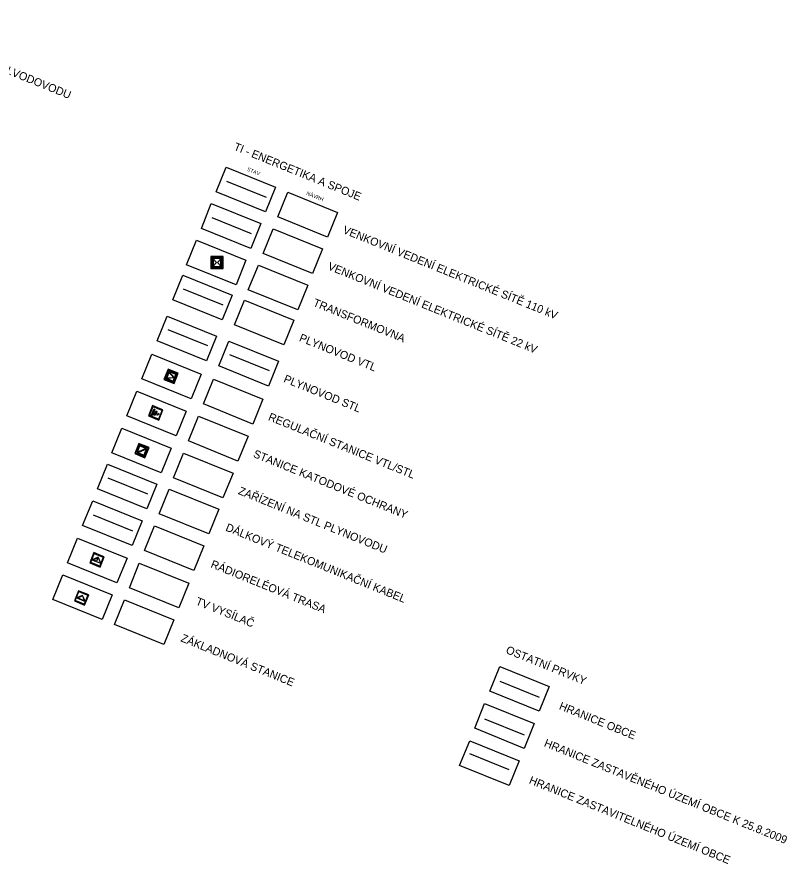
# Model space of a CAD drawing. Extents: x -522763 to -519637, y -1191176 to -1188936.
# Drawn here: x -521081 to -519637, y -1191176 to -1189587 of the extents above; entities that cross this region are included whole.
import ezdxf

# ---------------------------------------------------------------- set-up
doc = ezdxf.new("R2010")
doc.units = 0
for name, color, linetype in [('elved_110_s', 7, 'Continuous'), ('elved_22_s', 7, 'Continuous'), ('hr_ku_P_s', 7, 'Continuous'), ('hr_zast_uz_P_n', 7, 'Continuous'), ('HZU_P_s', 7, 'Continuous'), ('Implicitní', 7, 'Continuous'), ('kabel_dal_s', 7, 'Continuous'), ('ložisk_nerost', 7, 'Continuous'), ('plyn_STL_n', 7, 'Continuous'), ('plyn_STL_s', 7, 'Continuous'), ('plyn_VTL_s', 7, 'Continuous'), ('plyn_zar_STL_s', 7, 'Continuous'), ('RR_trasa_s', 7, 'Continuous'), ('stan_KO_s', 7, 'Continuous'), ('TV_vysilac_s', 7, 'Continuous'), ('zakl_stan_s', 7, 'Continuous')]:
    doc.layers.add(name, color=color, linetype=linetype)

msp = doc.modelspace()

# ---------------------------------------------------------------- linework, layer by layer
at = {"layer": 'elved_110_s'}
msp.add_line((-520688.1, -1189895), (-520613.9, -1189925.1), dxfattribs=at)
at = {"layer": 'elved_22_s'}
msp.add_line((-520715.9, -1189963.3), (-520641.8, -1189993.3), dxfattribs=at)
at = {"layer": 'hr_ku_P_s'}
msp.add_line((-520175.8, -1190832.8), (-520101.7, -1190862.8), dxfattribs=at)
at = {"layer": 'hr_zast_uz_P_n'}
msp.add_line((-520232.8, -1190968.4), (-520158.6, -1190998.4), dxfattribs=at)
at = {"layer": 'HZU_P_s'}
msp.add_line((-520204.4, -1190903.3), (-520130.3, -1190933.4), dxfattribs=at)
at = {"layer": 'Implicitní'}
for points in [[(-520688.9, -1189869.1), (-520596.2, -1189906.7), (-520615, -1189953), (-520707.7, -1189915.5)], [(-520573, -1189916.1), (-520480.4, -1189953.7), (-520499.1, -1190000), (-520591.8, -1189962.4)], [(-520716.8, -1189937.4), (-520624.1, -1189974.9), (-520642.9, -1190021.3), (-520735.5, -1189983.7)], [(-520600.9, -1189984.3), (-520508.2, -1190021.9), (-520527, -1190068.2), (-520619.7, -1190030.7)], [(-520744.4, -1190005.7), (-520651.8, -1190043.2), (-520670.5, -1190089.6), (-520763.2, -1190052)], [(-520628.6, -1190052.6), (-520535.9, -1190090.2), (-520554.7, -1190136.5), (-520647.4, -1190099)], [(-520770.4, -1190071.4), (-520677.7, -1190109), (-520696.5, -1190155.3), (-520789.2, -1190117.7)], [(-520654.6, -1190118.3), (-520561.9, -1190155.9), (-520580.7, -1190202.2), (-520673.4, -1190164.7)], [(-520799.6, -1190148.4), (-520706.9, -1190186), (-520725.7, -1190232.3), (-520818.4, -1190194.8)], [(-520683.7, -1190195.4), (-520591.1, -1190233), (-520609.8, -1190279.3), (-520702.5, -1190241.7)], [(-520828.5, -1190219.7), (-520735.8, -1190257.3), (-520754.6, -1190303.6), (-520847.3, -1190266.1)], [(-520712.6, -1190266.7), (-520620, -1190304.2), (-520638.7, -1190350.6), (-520731.4, -1190313)], [(-520856.6, -1190289), (-520763.9, -1190326.6), (-520782.7, -1190372.9), (-520875.4, -1190335.4)], [(-520740.7, -1190336), (-520648, -1190373.5), (-520666.8, -1190419.9), (-520759.5, -1190382.3)], [(-520884.7, -1190358.3), (-520792, -1190395.9), (-520810.8, -1190442.2), (-520903.4, -1190404.7)], [(-520768.8, -1190405.3), (-520676.1, -1190442.8), (-520694.9, -1190489.2), (-520787.6, -1190451.6)], [(-520911.4, -1190425.7), (-520818.8, -1190463.3), (-520837.5, -1190509.6), (-520930.2, -1190472)], [(-520795.6, -1190472.7), (-520702.9, -1190510.2), (-520721.7, -1190556.6), (-520814.4, -1190519)], [(-520939.3, -1190494.6), (-520846.7, -1190532.1), (-520865.4, -1190578.5), (-520958.1, -1190540.9)], [(-520939.3, -1190494.6), (-520846.7, -1190532.1), (-520865.4, -1190578.5), (-520958.1, -1190540.9)], [(-520823.5, -1190541.5), (-520730.8, -1190579.1), (-520749.6, -1190625.4), (-520842.3, -1190587.9)], [(-520967.6, -1190564.3), (-520874.9, -1190601.9), (-520893.7, -1190648.2), (-520986.4, -1190610.7)], [(-520851.8, -1190611.3), (-520759.1, -1190648.8), (-520777.9, -1190695.2), (-520870.5, -1190657.6)], [(-520995.5, -1190633.2), (-520902.8, -1190670.7), (-520921.6, -1190717.1), (-521014.3, -1190679.5)], [(-520995.5, -1190633.2), (-520902.8, -1190670.7), (-520921.6, -1190717.1), (-521014.3, -1190679.5)], [(-520879.7, -1190680.1), (-520787, -1190717.7), (-520805.8, -1190764), (-520898.4, -1190726.5)], [(-520176, -1190805.2), (-520083.3, -1190842.7), (-520102.1, -1190889.1), (-520194.8, -1190851.5)], [(-520204.2, -1190874.7), (-520111.5, -1190912.2), (-520130.3, -1190958.6), (-520222.9, -1190921)], [(-520232.3, -1190944.2), (-520139.6, -1190981.8), (-520158.4, -1191028.1), (-520251.1, -1190990.5)]]:
    msp.add_lwpolyline(points, close=True, dxfattribs=at)
at = {"layer": 'kabel_dal_s'}
msp.add_line((-520910.6, -1190451.6), (-520836.5, -1190481.7), dxfattribs=at)
at = {"layer": 'ložisk_nerost'}
for p, q in [((-520714.1, -1190047.7), (-520713.4, -1190047.7)), ((-520713.4, -1190047.7), (-520714.1, -1190047.7)), ((-520706.8, -1190047.7), (-520713.4, -1190041.1)), ((-520713.4, -1190054.4), (-520706.8, -1190047.7)), ((-520698.8, -1190041.1), (-520705.4, -1190047.7)), ((-520705.4, -1190047.7), (-520698.8, -1190054.4)), ((-520698.1, -1190047.7), (-520698.8, -1190047.7)), ((-520698.8, -1190047.7), (-520698.1, -1190047.7))]:
    msp.add_line(p, q, dxfattribs=at)
for points in [[(-520706.2, -1190036.3), (-520717.6, -1190036.3), (-520717.6, -1190059.2), (-520694.7, -1190059.2), (-520694.7, -1190036.3), (-520706.1, -1190036.3)], [(-520716.2, -1190037.7), (-520696.1, -1190037.7), (-520696.1, -1190057.8), (-520716.2, -1190057.8), (-520716.2, -1190037.7)], [(-520706.1, -1190037.7), (-520696.1, -1190037.7), (-520696.1, -1190057.8), (-520716.2, -1190057.8), (-520716.2, -1190037.7), (-520706.2, -1190037.7)], [(-520706.2, -1190037.7), (-520706.2, -1190036.3)], [(-520706.1, -1190036.3), (-520706.1, -1190037.7)], [(-520714.1, -1190047.7), (-520714.1, -1190039.7), (-520706.1, -1190039.7)], [(-520706.1, -1190055.8), (-520714.1, -1190055.8), (-520714.1, -1190047.7)], [(-520713.4, -1190041.1), (-520713.4, -1190047.7)], [(-520713.4, -1190047.7), (-520713.4, -1190054.4)], [(-520706.1, -1190039.7), (-520698.1, -1190039.7), (-520698.1, -1190047.7)], [(-520698.1, -1190047.7), (-520698.1, -1190055.8), (-520706.1, -1190055.8)], [(-520698.8, -1190047.7), (-520698.8, -1190041.1)], [(-520698.8, -1190054.4), (-520698.8, -1190047.7)], [(-520788.4, -1190251.5), (-520798, -1190247.6), (-520805.8, -1190266.9), (-520786.5, -1190274.7), (-520778.7, -1190255.4), (-520788.4, -1190251.5)], [(-520797.3, -1190249.3), (-520780.4, -1190256.1), (-520787.2, -1190273), (-520804.1, -1190266.2), (-520797.3, -1190249.3)], [(-520788.9, -1190252.7), (-520780.4, -1190256.1), (-520787.2, -1190273), (-520804.1, -1190266.2), (-520797.3, -1190249.3), (-520788.9, -1190252.7)], [(-520794.8, -1190268), (-520801.6, -1190265.2), (-520798.9, -1190258.5)], [(-520798.3, -1190258.7), (-520800.5, -1190264.2)], [(-520798.9, -1190258.5), (-520796.2, -1190251.7), (-520789.4, -1190254.4)], [(-520798.9, -1190258.5), (-520798.3, -1190258.7)], [(-520798.3, -1190258.7), (-520798.9, -1190258.5)], [(-520796.1, -1190253.3), (-520798.3, -1190258.7)], [(-520787.4, -1190263.1), (-520796.1, -1190253.3)], [(-520789.7, -1190255), (-520795.8, -1190252.5)], [(-520795.8, -1190252.5), (-520786, -1190263.7)], [(-520789.4, -1190254.4), (-520789.7, -1190255)], [(-520789.6, -1190255), (-520789.4, -1190254.5)], [(-520783.5, -1190257.5), (-520789.6, -1190255)], [(-520789.4, -1190254.5), (-520782.7, -1190257.2), (-520785.4, -1190263.9)], [(-520788.4, -1190251.5), (-520788.9, -1190252.7)], [(-520788.9, -1190252.7), (-520788.4, -1190251.5)], [(-520788.5, -1190269.9), (-520783.5, -1190257.5)], [(-520786, -1190263.7), (-520800.8, -1190264.9)], [(-520800.8, -1190264.9), (-520794.6, -1190267.4)], [(-520800.5, -1190264.2), (-520787.4, -1190263.1)], [(-520785.4, -1190263.9), (-520788.1, -1190270.7), (-520794.8, -1190268)], [(-520794.6, -1190267.4), (-520788.5, -1190269.9)]]:
    msp.add_lwpolyline(points, dxfattribs=at)
at = {"layer": 'plyn_STL_n'}
msp.add_line((-520682.5, -1190220.3), (-520608.4, -1190250.4), dxfattribs=at)
at = {"layer": 'plyn_STL_s'}
msp.add_line((-520798.4, -1190173.4), (-520724.2, -1190203.4), dxfattribs=at)
at = {"layer": 'plyn_VTL_s'}
msp.add_line((-520769.6, -1190097.3), (-520695.5, -1190127.3), dxfattribs=at)
at = {"layer": 'plyn_zar_STL_s'}
for p, q in [((-520847.5, -1190400.1), (-520855.4, -1190403.4)), ((-520855, -1190404.3), (-520847.2, -1190401)), ((-520838.9, -1190396.5), (-520847.5, -1190400.1)), ((-520847.2, -1190401), (-520838.5, -1190397.3)), ((-520844.4, -1190394.2), (-520844.2, -1190393.6)), ((-520844.2, -1190393.6), (-520844.4, -1190394.2)), ((-520849.7, -1190407.1), (-520849.5, -1190406.5)), ((-520849.4, -1190406.6), (-520849.7, -1190407.1))]:
    msp.add_line(p, q, dxfattribs=at)
for points in [[(-520843.1, -1190390.7), (-520852.7, -1190386.8), (-520860.5, -1190406.1), (-520841.2, -1190413.9), (-520833.4, -1190394.6), (-520843, -1190390.7)], [(-520852, -1190388.5), (-520835.1, -1190395.3), (-520841.9, -1190412.2), (-520858.8, -1190405.4), (-520852, -1190388.5)], [(-520843.5, -1190391.9), (-520835.1, -1190395.3), (-520841.9, -1190412.2), (-520858.8, -1190405.4), (-520852, -1190388.5), (-520843.5, -1190391.9)], [(-520853.7, -1190397.6), (-520856.4, -1190404.4), (-520849.7, -1190407.1)], [(-520855.4, -1190403.4), (-520853.1, -1190397.9)], [(-520849.5, -1190406.5), (-520855, -1190404.3)], [(-520844.2, -1190393.6), (-520851, -1190390.9), (-520853.7, -1190397.6)], [(-520853.1, -1190397.9), (-520850.6, -1190391.7)], [(-520850.6, -1190391.7), (-520844.4, -1190394.2)], [(-520849.7, -1190407.1), (-520842.9, -1190409.9), (-520840.2, -1190403.1)], [(-520844.4, -1190394.2), (-520838.9, -1190396.5)], [(-520840.2, -1190403.1), (-520837.5, -1190396.4), (-520844.2, -1190393.6)], [(-520843, -1190390.7), (-520843.5, -1190391.9)], [(-520843.5, -1190391.9), (-520843.1, -1190390.7)], [(-520840.8, -1190402.9), (-520843.3, -1190409)], [(-520838.5, -1190397.3), (-520840.8, -1190402.9)], [(-520843.3, -1190409), (-520849.4, -1190406.6)]]:
    msp.add_lwpolyline(points, dxfattribs=at)
at = {"layer": 'RR_trasa_s'}
msp.add_line((-520938.5, -1190520.5), (-520864.4, -1190550.5), dxfattribs=at)
at = {"layer": 'stan_KO_s'}
for points in [[(-520817.2, -1190320), (-520826.8, -1190316.1), (-520834.7, -1190335.4), (-520815.4, -1190343.2), (-520807.6, -1190323.9), (-520817.2, -1190320)], [(-520826.1, -1190317.8), (-520809.2, -1190324.6), (-520816.1, -1190341.5), (-520833, -1190334.7), (-520826.1, -1190317.8)], [(-520817.7, -1190321.2), (-520809.2, -1190324.6), (-520816.1, -1190341.5), (-520833, -1190334.7), (-520826.1, -1190317.8), (-520817.7, -1190321.2)], [(-520829.3, -1190334.7), (-520824, -1190321.8)], [(-520822.6, -1190323.4), (-520827, -1190334.5)], [(-520824, -1190321.8), (-520822.6, -1190323.4)], [(-520817.2, -1190320), (-520817.7, -1190321.2)], [(-520817.7, -1190321.2), (-520817.2, -1190320)], [(-520827, -1190334.5), (-520829.3, -1190334.7)], [(-520823.7, -1190334.2), (-520820.3, -1190326)], [(-520821.5, -1190334.1), (-520823.7, -1190334.2)], [(-520818.9, -1190327.6), (-520821.5, -1190334.1)], [(-520820.3, -1190326), (-520818.9, -1190327.6)], [(-520818.1, -1190333.8), (-520816.6, -1190330.2)], [(-520815.9, -1190333.6), (-520818.1, -1190333.8)], [(-520816.6, -1190330.2), (-520815.2, -1190331.8)], [(-520815.2, -1190331.8), (-520815.9, -1190333.6)]]:
    msp.add_lwpolyline(points, dxfattribs=at)
at = {"layer": 'TV_vysilac_s'}
for points in [[(-520927.2, -1190595.5), (-520936.9, -1190591.6), (-520944.7, -1190610.9), (-520925.4, -1190618.7), (-520917.6, -1190599.4), (-520927.2, -1190595.5)], [(-520936.2, -1190593.3), (-520919.3, -1190600.1), (-520926.1, -1190617), (-520943, -1190610.2), (-520936.2, -1190593.3)], [(-520927.7, -1190596.7), (-520919.3, -1190600.1), (-520926.1, -1190617), (-520943, -1190610.2), (-520936.2, -1190593.3), (-520927.7, -1190596.7)], [(-520934.4, -1190602.7), (-520940.3, -1190605.2)], [(-520940.3, -1190605.2), (-520932.6, -1190608.3)], [(-520938.7, -1190605), (-520934.2, -1190603.1)], [(-520932, -1190607.8), (-520938.7, -1190605)], [(-520926.6, -1190605.8), (-520929, -1190600.4), (-520934.4, -1190602.7)], [(-520934.4, -1190602.7), (-520934.2, -1190603.1)], [(-520934.2, -1190603.1), (-520934.4, -1190602.7)], [(-520934.2, -1190603.1), (-520929.2, -1190601)], [(-520932.6, -1190608.3), (-520924.1, -1190611.7)], [(-520929.2, -1190601), (-520932, -1190607.8)], [(-520927.2, -1190595.5), (-520927.7, -1190596.7)], [(-520927.7, -1190596.7), (-520927.2, -1190595.5)], [(-520924.1, -1190611.7), (-520926.6, -1190605.8)]]:
    msp.add_lwpolyline(points, dxfattribs=at)
at = {"layer": 'zakl_stan_s'}
for points in [[(-520956.2, -1190667), (-520965.8, -1190663.1), (-520973.6, -1190682.3), (-520954.4, -1190690.2), (-520946.6, -1190670.9), (-520956.2, -1190667)], [(-520965.1, -1190664.7), (-520948.2, -1190671.6), (-520955.1, -1190688.5), (-520972, -1190681.6), (-520965.1, -1190664.7)], [(-520956.7, -1190668.2), (-520948.2, -1190671.6), (-520955.1, -1190688.5), (-520972, -1190681.6), (-520965.1, -1190664.7), (-520956.7, -1190668.2)], [(-520963.6, -1190674.2), (-520969.5, -1190676.7)], [(-520955.8, -1190677.3), (-520958.1, -1190671.9), (-520963.6, -1190674.2)], [(-520963.4, -1190674.6), (-520958.4, -1190672.5)], [(-520958.4, -1190672.5), (-520956.3, -1190677.5)], [(-520956.2, -1190667), (-520956.7, -1190668.2)], [(-520956.7, -1190668.2), (-520956.2, -1190667)], [(-520969.5, -1190676.7), (-520961.7, -1190679.8)], [(-520967.8, -1190676.5), (-520963.4, -1190674.6)], [(-520960.8, -1190679.4), (-520967.8, -1190676.5)], [(-520961.7, -1190679.8), (-520953.3, -1190683.2)], [(-520954.4, -1190682), (-520960.8, -1190679.4)], [(-520956.3, -1190677.5), (-520955.8, -1190677.3)], [(-520955.8, -1190677.3), (-520956.3, -1190677.5)], [(-520956.3, -1190677.5), (-520954.4, -1190682)], [(-520953.3, -1190683.2), (-520955.8, -1190677.3)]]:
    msp.add_lwpolyline(points, dxfattribs=at)

# ---------------------------------------------------------------- texts
at = {"layer": 'Implicitní'}
for s, height, rotation, p in [('VODOVODNÍ ŘAD SKUPIN.VODOVODU', 15, 337.9379, (-521329.6, -1189601.2)), ('TI - ENERGETIKA A SPOJE', 15, 337.9379, (-520676, -1189836.2)), ('STAV', 7, 337.9379, (-520650.5, -1189875.5)), ('NÁVRH', 7, 337.9379, (-520539.4, -1189920.6)), ('VENKOVNÍ VEDENÍ ELEKTRICKÉ SÍTĚ 110 kV', 15, 337.9379, (-520471.7, -1189992.2)), ('VENKOVNÍ VEDENÍ ELEKTRICKÉ SÍTĚ 22 kV', 15, 337.9379, (-520499.6, -1190060.4)), ('TRANSFORMOVNA', 15, 337.9379, (-520527.3, -1190128.7)), ('PLYNOVOD VTL', 15, 337.9379, (-520553.3, -1190194.5)), ('PLYNOVOD STL', 15, 337.9379, (-520582.5, -1190271.5)), ('REGULAČNÍ STANICE VTL/STL', 15, 337.9379, (-520611.3, -1190342.8)), ('STANICE KATODOVÉ OCHRANY', 15, 337.9379, (-520639.4, -1190412.1)), ('ZAŘÍZENÍ NA STL PLYNOVODU', 15, 337.9379, (-520667.5, -1190481.4)), ('DÁLKOVÝ TELEKOMUNIKAČNÍ KABEL', 15, 337.9379, (-520691.3, -1190550)), ('RÁDIORELÉOVÁ TRASA', 15, 337.9379, (-520719.2, -1190618.9)), ('TV VYSÍLAČ', 15, 337.9379, (-520747.4, -1190688.6)), ('ZÁKLADNOVÁ STANICE', 15, 337.9379, (-520775.4, -1190757.5)), ('OSTATNÍ PRVKY', 15, 337.9381, (-520165.7, -1190779.7)), ('HRANICE OBCE', 15, 337.9381, (-520065.9, -1190884.9)), ('HRANICE ZASTAVĚNÉHO ÚZEMÍ OBCE K 25.8.2009', 15, 337.9381, (-520094.1, -1190954.4)), ('HRANICE ZASTAVITELNÉHO ÚZEMÍ OBCE', 15, 337.9381, (-520122.2, -1191023.9))]:
    msp.add_text(s, height=height, rotation=rotation, dxfattribs=at).set_placement(p)

doc.saveas('drawing.dxf')
